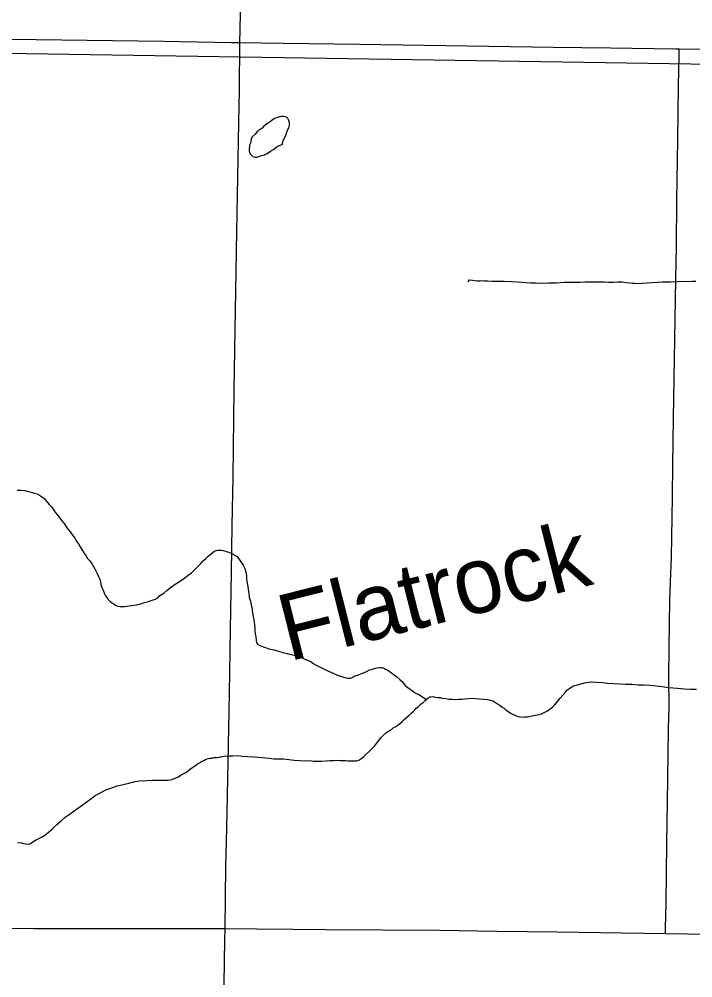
# Model space of a CAD drawing. Extents: x 0 to 64.8, y -5 to 22.
# Drawn here: x 7.424 to 8.193, y 14.689 to 15.783 of the extents above; entities that cross this region are included whole.
import ezdxf

# ---------------------------------------------------------------- set-up
doc = ezdxf.new("R2010")
doc.units = 0
for name, color, linetype in [('GM_X_County_Road', 7, 'Continuous'), ('GM_X_Minor_Lake', 7, 'Continuous'), ('GM_X_Minor_Lake_Text', 7, 'Continuous'), ('GM_X_Minor_River', 7, 'Continuous'), ('GM_X_State_Route', 7, 'Continuous'), ('GM_X_Township_Road', 7, 'Continuous')]:
    doc.layers.add(name, color=color, linetype=linetype)

msp = doc.modelspace()

# ---------------------------------------------------------------- linework, layer by layer
at = {"layer": 'GM_X_County_Road'}
for points in [[(7.6594, 14.7455), (7.6603, 14.8164), (7.6615, 14.8599), (7.662, 14.8972), (7.6639, 14.9936), (7.6646, 15.0371), (7.6654, 15.0868), (7.6666, 15.152), (7.6676, 15.2049), (7.6684, 15.2608), (7.6698, 15.3603), (7.6729, 15.5405), (7.6752, 15.6648), (7.6757, 15.7021), (7.6763, 15.7559)], [(7.6492, 14.1), (7.6496, 14.1235), (7.6508, 14.1856), (7.6515, 14.2291), (7.6524, 14.285), (7.6532, 14.3379), (7.6543, 14.4156), (7.6564, 14.5492), (7.6573, 14.6082), (7.6592, 14.7325), (7.6594, 14.7455)]]:
    msp.add_lwpolyline(points, dxfattribs=at)
at = {"layer": 'GM_X_Minor_Lake'}
for points in [[(7.7243, 15.6397), (7.7247, 15.6409), (7.7255, 15.6443), (7.7271, 15.6469), (7.7287, 15.6503), (7.7295, 15.6525), (7.7307, 15.6559), (7.7319, 15.6585), (7.7327, 15.6616), (7.7328, 15.6646), (7.7321, 15.6669), (7.7306, 15.67), (7.7284, 15.6712), (7.7265, 15.6716), (7.7235, 15.6717), (7.7215, 15.6713), (7.7185, 15.6702), (7.7158, 15.6692), (7.7131, 15.6673), (7.7108, 15.6655), (7.7085, 15.664), (7.7065, 15.6629), (7.703, 15.66), (7.7015, 15.6581), (7.6992, 15.6566), (7.6968, 15.6552), (7.6937, 15.6514), (7.6902, 15.6485), (7.689, 15.6458), (7.6882, 15.6413), (7.6873, 15.6387), (7.6873, 15.6368), (7.6869, 15.6349), (7.6868, 15.6322), (7.6879, 15.6288), (7.6909, 15.626), (7.6935, 15.6252), (7.6954, 15.6252), (7.6988, 15.6262), (7.7011, 15.627), (7.7042, 15.628), (7.7065, 15.6291), (7.7084, 15.6302), (7.7111, 15.632), (7.7146, 15.6339), (7.7169, 15.6357), (7.7193, 15.6376), (7.7243, 15.6397)], [(7.7243, 15.6397), (7.7247, 15.6409), (7.7255, 15.6443), (7.7271, 15.6469), (7.7287, 15.6503), (7.7295, 15.6525), (7.7307, 15.6559), (7.7319, 15.6585), (7.7327, 15.6616), (7.7328, 15.6646), (7.7321, 15.6669), (7.7306, 15.67), (7.7284, 15.6712), (7.7265, 15.6716), (7.7235, 15.6717), (7.7215, 15.6713), (7.7185, 15.6702), (7.7158, 15.6692), (7.7131, 15.6673), (7.7108, 15.6655), (7.7085, 15.664), (7.7065, 15.6629), (7.703, 15.66), (7.7015, 15.6581)], [(7.7015, 15.6581), (7.6992, 15.6566), (7.6968, 15.6552), (7.6937, 15.6514), (7.6902, 15.6485), (7.689, 15.6458), (7.6882, 15.6413), (7.6873, 15.6387), (7.6873, 15.6368), (7.6869, 15.6349), (7.6868, 15.6322), (7.6879, 15.6288), (7.6909, 15.626), (7.6935, 15.6252), (7.6954, 15.6252), (7.6988, 15.6262), (7.7011, 15.627), (7.7042, 15.628), (7.7065, 15.6291), (7.7084, 15.6302), (7.7111, 15.632), (7.7146, 15.6339), (7.7169, 15.6357), (7.7193, 15.6376), (7.7243, 15.6397)]]:
    msp.add_lwpolyline(points, dxfattribs=at)
at = {"layer": 'GM_X_Minor_River'}
for points in [[(8.9, 15.7203), (5.6224, 15.7712)], [(8.1807, 15.4832), (8.1754, 15.4829), (8.1678, 15.4827), (8.1632, 15.4825), (8.1583, 15.4826), (8.1526, 15.4823), (8.1465, 15.4817), (8.1408, 15.4814), (8.1347, 15.4812), (8.1301, 15.4809), (8.1267, 15.481), (8.1237, 15.4811), (8.1206, 15.4815), (8.1168, 15.482), (8.1127, 15.4825), (8.1073, 15.4826), (8.102, 15.4823), (8.0967, 15.4824), (8.0921, 15.4825), (8.0876, 15.4826), (8.0838, 15.4827), (8.0796, 15.4828), (8.075, 15.4826), (8.0701, 15.4827), (8.064, 15.4824), (8.0541, 15.4823), (8.0461, 15.4821), (8.0374, 15.4815), (8.0286, 15.4813), (8.0202, 15.4811), (8.0134, 15.4813), (8.0081, 15.4814), (7.9925, 15.4825), (7.9861, 15.483), (7.9777, 15.4832), (7.9712, 15.4834), (7.9644, 15.4835), (7.9591, 15.4836), (7.9549, 15.4837), (7.9526, 15.4842), (7.9503, 15.4838), (7.9465, 15.4839), (7.9416, 15.4844), (7.9378, 15.4849), (7.9371, 15.4849), (7.9371, 15.4845), (7.9371, 15.4845), (7.9363, 15.4826)], [(8.1963, 15.4832), (8.1918, 15.4833), (8.1861, 15.4831), (8.1807, 15.4832)], [(7.4221, 15.2455), (7.4263, 15.2454), (7.4305, 15.2449), (7.4346, 15.244), (7.438, 15.2432), (7.4414, 15.242), (7.4448, 15.2411), (7.4475, 15.2399), (7.4501, 15.2384), (7.4527, 15.2364), (7.4549, 15.2337), (7.4568, 15.2314), (7.459, 15.2287), (7.4608, 15.2267), (7.4634, 15.2236), (7.4645, 15.2217), (7.4668, 15.219), (7.469, 15.2163), (7.4708, 15.2136), (7.473, 15.2105), (7.4756, 15.2074), (7.4789, 15.2024), (7.4826, 15.1981), (7.4852, 15.1943), (7.4878, 15.1908), (7.49, 15.1873), (7.4922, 15.1842), (7.494, 15.1808), (7.4962, 15.1769), (7.4984, 15.1738), (7.5006, 15.1708), (7.5025, 15.1677), (7.5051, 15.165), (7.5076, 15.1611), (7.5095, 15.1576), (7.5117, 15.1542), (7.5135, 15.1503), (7.5149, 15.1469), (7.5164, 15.1438), (7.5171, 15.1408), (7.5177, 15.1377), (7.5188, 15.1346), (7.5199, 15.132), (7.5213, 15.1285), (7.5228, 15.1251), (7.5246, 15.1231), (7.5257, 15.1212), (7.5287, 15.1181), (7.5351, 15.1141), (7.537, 15.1133), (7.5396, 15.1129), (7.5415, 15.1129), (7.5446, 15.1128), (7.5468, 15.1131), (7.5499, 15.1134), (7.5533, 15.1141), (7.5583, 15.1148), (7.5633, 15.1158), (7.5675, 15.1172), (7.5721, 15.1186), (7.5763, 15.1201), (7.5801, 15.1211), (7.5828, 15.1226), (7.5851, 15.1252), (7.5894, 15.1281), (7.5929, 15.1311), (7.5971, 15.1344), (7.6014, 15.1373), (7.6056, 15.1403), (7.6095, 15.1429), (7.6134, 15.1454), (7.6172, 15.1484), (7.6211, 15.1513), (7.6242, 15.1543), (7.6269, 15.1569), (7.6297, 15.1599), (7.6316, 15.1617), (7.6343, 15.1647), (7.6374, 15.1677), (7.6402, 15.1703), (7.6433, 15.1729), (7.6464, 15.1754), (7.649, 15.1765), (7.651, 15.1769), (7.6529, 15.1772), (7.6551, 15.1771), (7.657, 15.1767), (7.6597, 15.1759), (7.6634, 15.1747), (7.6672, 15.1731), (7.6706, 15.1715), (7.6732, 15.1699)], [(7.6732, 15.1699), (7.6798, 15.1599), (7.6817, 15.156), (7.6831, 15.1518), (7.6837, 15.1476), (7.6837, 15.1446), (7.684, 15.1416), (7.6847, 15.1389), (7.6854, 15.1354), (7.6857, 15.132), (7.6863, 15.1278), (7.687, 15.1229), (7.6884, 15.1187), (7.6891, 15.1145), (7.6901, 15.1099), (7.6908, 15.1049), (7.6918, 15.1), (7.6924, 15.0954), (7.6931, 15.0916), (7.6934, 15.0882), (7.6933, 15.0851), (7.6936, 15.0817), (7.6943, 15.0786), (7.695, 15.0741), (7.6953, 15.0718), (7.6964, 15.0699), (7.699, 15.0683), (7.7028, 15.0667), (7.7055, 15.0659), (7.7092, 15.0646), (7.7153, 15.0634), (7.7202, 15.0617), (7.7251, 15.0605), (7.73, 15.0592), (7.7342, 15.058), (7.738, 15.0572), (7.7414, 15.0563), (7.7444, 15.0551), (7.7474, 15.0543), (7.7504, 15.0527), (7.7534, 15.0515), (7.7575, 15.0495), (7.7605, 15.0475), (7.7639, 15.0456), (7.7677, 15.0436), (7.7718, 15.0416), (7.7876, 15.0344), (7.7933, 15.0324), (7.7974, 15.0315), (7.7993, 15.0311), (7.8024, 15.031), (7.8043, 15.0317), (7.8078, 15.0336), (7.8116, 15.035), (7.815, 15.0364), (7.8185, 15.0375), (7.8216, 15.0389), (7.8243, 15.0404), (7.8269, 15.0411), (7.8296, 15.0422), (7.8323, 15.0429), (7.8357, 15.0432), (7.838, 15.0431), (7.8403, 15.0423), (7.8422, 15.0415), (7.8444, 15.0407), (7.8467, 15.0391), (7.8493, 15.0372), (7.8523, 15.0348), (7.8553, 15.0325), (7.8586, 15.0297), (7.8616, 15.027), (7.8649, 15.0228), (7.8694, 15.0193), (7.8728, 15.0169), (7.8754, 15.0149), (7.8776, 15.0137), (7.8803, 15.0125), (7.889, 15.0066)], [(8.0243, 14.9922), (8.027, 14.9937), (8.0301, 14.9959), (8.0328, 14.9981), (8.0351, 15.0003), (8.0375, 15.0029), (8.0394, 15.0055), (8.0418, 15.0082), (8.0476, 15.0152), (8.0492, 15.0175), (8.0515, 15.0189), (8.055, 15.0211), (8.0569, 15.0222), (8.06, 15.0229), (8.063, 15.024), (8.0657, 15.0247), (8.0695, 15.0258), (8.0734, 15.0264), (8.0779, 15.0267), (8.0829, 15.0266), (8.0901, 15.0261), (8.0958, 15.0255), (8.1026, 15.025), (8.1094, 15.0245), (8.1163, 15.0243), (8.1235, 15.0242), (8.1307, 15.0236), (8.1375, 15.0235), (8.1444, 15.0229), (8.1512, 15.0224), (8.158, 15.0215), (8.1652, 15.0206), (8.1755, 15.0196), (8.1831, 15.019), (8.1903, 15.0185), (8.1971, 15.0187)], [(7.673, 14.9428), (7.6787, 14.9423), (7.6851, 14.9417), (7.6931, 14.9412), (7.7098, 14.9397), (7.7151, 14.9392), (7.7204, 14.939), (7.7261, 14.9389), (7.7322, 14.9384), (7.7383, 14.9375), (7.7443, 14.937), (7.7497, 14.9369), (7.7557, 14.9371), (7.7603, 14.9366), (7.7649, 14.9365), (7.7698, 14.9364), (7.7747, 14.9367), (7.7789, 14.9373), (7.7835, 14.9372), (7.7873, 14.9375), (7.7907, 14.9371), (7.7938, 14.937), (7.7968, 14.9373), (7.7991, 14.9369), (7.8017, 14.9368), (7.8044, 14.9368), (7.8071, 14.9367), (7.8093, 14.9367), (7.812, 14.9374), (7.8155, 14.9399), (7.8178, 14.9418), (7.8205, 14.9444), (7.824, 14.9477), (7.8272, 14.9507), (7.8299, 14.9537), (7.8322, 14.9567), (7.8346, 14.96), (7.8373, 14.9634), (7.8401, 14.966), (7.8424, 14.9682), (7.8447, 14.97), (7.847, 14.9715), (7.8493, 14.9726), (7.8513, 14.9745), (7.854, 14.9759), (7.8563, 14.9774), (7.8582, 14.9789), (7.8613, 14.9818), (7.8633, 14.9837), (7.8695, 14.9889), (7.8714, 14.9907), (7.8741, 14.9929), (7.8757, 14.9948), (7.8772, 14.9967), (7.8792, 14.9981), (7.8811, 15), (7.8831, 15.0019), (7.8854, 15.0033), (7.8881, 15.0059), (7.8908, 15.0081), (7.8931, 15.0096), (7.8966, 15.0103), (7.8988, 15.0095), (7.9022, 15.009), (7.9049, 15.009), (7.9072, 15.0081), (7.9113, 15.0077), (7.9147, 15.0072), (7.9186, 15.0071), (7.922, 15.0067), (7.9258, 15.007), (7.9296, 15.0073), (7.9334, 15.0076), (7.9376, 15.0078), (7.9418, 15.0081), (7.9456, 15.008), (7.9494, 15.0076), (7.9543, 15.0071), (7.9585, 15.0066), (7.9623, 15.0061), (7.9656, 15.0049), (7.9679, 15.0034), (7.9701, 15.0018), (7.9728, 15.0002), (7.975, 14.9983), (7.9776, 14.9967), (7.9802, 14.9947), (7.9829, 14.9928), (7.9859, 14.9908), (7.99, 14.9888), (7.9934, 14.9872), (7.9964, 14.9868), (7.9983, 14.9867), (8.001, 14.987), (8.004, 14.987), (8.0071, 14.9873), (8.0097, 14.988), (8.0136, 14.989), (8.0174, 14.9897), (8.0204, 14.9904), (8.0243, 14.9922)], [(7.4225, 14.8436), (7.427, 14.8431), (7.4293, 14.8427), (7.4338, 14.8418), (7.4365, 14.8421), (7.44, 14.8443), (7.443, 14.8462), (7.4461, 14.848), (7.45, 14.8498), (7.4538, 14.852), (7.4577, 14.8549), (7.462, 14.859), (7.4674, 14.8642), (7.4724, 14.8683), (7.4771, 14.8724), (7.4814, 14.8757), (7.4856, 14.8786), (7.4899, 14.8816), (7.4937, 14.8845), (7.5045, 14.8923), (7.5076, 14.8945), (7.5111, 14.8974), (7.5157, 14.8996), (7.5192, 14.9014), (7.5234, 14.9036), (7.5277, 14.9054), (7.5319, 14.9068), (7.5361, 14.9083), (7.5399, 14.9089), (7.5445, 14.91), (7.5495, 14.9114), (7.5552, 14.9128), (7.5613, 14.9138), (7.5697, 14.9143), (7.5758, 14.9146), (7.5811, 14.9148), (7.5864, 14.9147), (7.5906, 14.9146), (7.594, 14.9149), (7.5967, 14.9152), (7.599, 14.9156), (7.6032, 14.9174), (7.6063, 14.9184), (7.6094, 14.921), (7.614, 14.9232), (7.6171, 14.9254), (7.6202, 14.928), (7.6233, 14.9298), (7.6256, 14.9313), (7.6279, 14.9332), (7.6302, 14.9346), (7.6325, 14.9361), (7.6352, 14.9372), (7.6371, 14.9383), (7.6391, 14.939), (7.6421, 14.9397), (7.6444, 14.94), (7.6467, 14.9407), (7.6494, 14.9406), (7.6528, 14.9409), (7.6555, 14.9416), (7.6585, 14.942), (7.6627, 14.9426), (7.6677, 14.9425), (7.673, 14.9428)]]:
    msp.add_lwpolyline(points, dxfattribs=at)
at = {"layer": 'GM_X_State_Route'}
msp.add_lwpolyline([(7.415, 15.7599), (7.5891, 15.7573), (7.6668, 15.7561), (7.6763, 15.7559), (7.7258, 15.755), (7.8129, 15.7539), (8.0336, 15.7506), (8.0989, 15.7498), (8.1735, 15.7487), (8.1774, 15.7486), (8.2512, 15.7474), (8.3289, 15.746), (8.3911, 15.745), (8.5185, 15.7429), (8.6056, 15.7416), (8.674, 15.7408), (8.6759, 15.7407), (8.7859, 15.7389), (8.8139, 15.7385), (8.9, 15.7373)], dxfattribs=at)
at = {"layer": 'GM_X_Township_Road'}
for points in [[(7.6763, 15.7559), (7.6764, 15.7704), (7.6787, 15.8854), (7.6791, 15.9196), (7.6817, 16.0221), (7.6824, 16.0687), (7.6831, 16.1278), (7.6846, 16.2117), (7.6864, 16.3049), (7.6873, 16.3639), (7.6908, 16.5504), (7.6918, 16.6063), (7.6925, 16.6405), (7.6936, 16.7026), (7.6939, 16.7306), (7.6945, 16.7553)], [(8.1618, 14.7399), (8.1619, 14.7462), (8.1624, 14.7742), (8.1635, 14.8426), (8.1639, 14.8892), (8.1654, 14.9731), (8.1658, 14.998), (8.1656, 15.0322), (8.1659, 15.0664), (8.1668, 15.1192), (8.1675, 15.1409), (8.1686, 15.1689), (8.1696, 15.2373), (8.1703, 15.2746), (8.171, 15.3274), (8.1723, 15.4176), (8.1735, 15.486), (8.1743, 15.5233), (8.1749, 15.5761), (8.1758, 15.6445), (8.1765, 15.7067), (8.1772, 15.7409), (8.1773, 15.744), (8.1774, 15.7486)], [(7.1581, 14.7456), (7.1894, 14.7457), (7.2547, 14.7459), (7.3137, 14.7458), (7.3884, 14.7459), (7.4412, 14.7455), (7.6495, 14.7457), (7.6594, 14.7455)], [(7.6594, 14.7455), (7.6961, 14.7451), (7.7366, 14.745), (7.7739, 14.7445), (7.9044, 14.7436), (7.9697, 14.7427), (8.0381, 14.7418), (8.1618, 14.7399)], [(8.1618, 14.7399), (8.2371, 14.7388), (8.3552, 14.7374), (8.3645, 14.7375), (8.3987, 14.7372), (8.4858, 14.7359), (8.5635, 14.735), (8.6004, 14.7342), (8.6509, 14.7334), (8.6626, 14.7332)]]:
    msp.add_lwpolyline(points, dxfattribs=at)

# ---------------------------------------------------------------- texts
at = {"layer": 'GM_X_Minor_Lake_Text'}
msp.add_text('Flatrock', height=0.0758, rotation=14.1987, dxfattribs=at).set_placement((7.7318, 15.0499))

doc.saveas('drawing.dxf')
